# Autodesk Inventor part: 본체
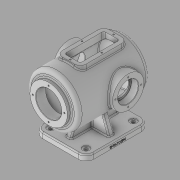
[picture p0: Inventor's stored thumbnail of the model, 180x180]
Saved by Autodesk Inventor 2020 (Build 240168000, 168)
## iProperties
Created: 2021-11
Part Number: 본체
Material: Generic
Document SubType Name: Modeling
Designer: Administrator
Density: 1 g/cm^3
Appearance: Default
Mass: 1311.12 g
Surface Area: 2404.68 cm^2
Volume: 1311.12 cm^3
Author: Administrator
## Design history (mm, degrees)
sketch "스케치1"
  geometry: L1 (-80, -65)-(80, -65); L2 (80, -65)-(80, 65); L3 (80, 65)-(-80, 65); L4 (-80, 65)-(-80, -65); L5 (-80, -65)-(80, 65); L6 (80, -65)-(-80, 65); 1 further point
  constraints: 12 end point, 2 midpoint, 2 parallel, 1 horizontal, 1 perpendicular
  dimensions: "d0" = 160 distance of L2.end L3.end; "d1" = 130 distance of L3.end L1.start
extrude "돌출1" new body sketch "스케치1" distance "d2" = 14; taper "d3" = 0 deg
sketch "스케치2"
  geometry: L1 (100, 179)-(-75.993, 179); L2 (-100, 114)-(110, 114); L3 (100, 179)-(100, 161.5); L4 (100, 161.5)-(110, 161.5); L5 (110, 161.5)-(110, 114); L6 (110, 146.5)-(85, 146.5); L7 (85, 146.5)-(85, 169); L8 (85, 169)-(-71.239, 169); L9 (80, 0)-(80, 14) reference; A1 r 100 centre (0, 114) between (-75.993, 179) and (-75.993, 49); A2 r 90 centre (0, 114) between (-71.239, 169) and (-75.514, 65.035); 2 further points
  constraints: 16 end point, 5 point on circle, 4 perpendicular, 2 centre point, 2 horizontal, 1 concentric, 1 parallel, 1 point on line, 1 vertical, 1 vertical alignment
  dimensions: "d4" = 210 distance of L2.start L2.end; "d5" = 95 diameter of L4 L2; "d6" = 100 radius of A1; "d7" = 114 vertical distance of point (0, 0) L2.end; "d8" = 10 distance of L3.end L4.end; "d9" = 130 diameter of L1 L2; "d10" = 10 radial gap between concentric circles of A1 A2; "d11" = 65 diameter of L6 L2; "d12" = 25 distance of L6.start L6.end; "d13" = 110 diameter of L8 L2; "d125" = 30 horizontal distance of L9.end L2.end
revolve "회전1" stored, may be unused: angle "d14" = 90 deg
sketch "스케치3"
  geometry: L1 (110, 66.5)-(110, 161.5) reference; C1 r 40 at (-17, 114); 2 further points
  constraints: 1 centre point, 1 horizontal alignment, 1 midpoint
  dimensions: "d15" = 80 diameter of C1; "d72" = 127 distance from line of C1.centre L1
extrude "돌출2" join sketch "스케치3" stored distance "d16" = 150; taper "d17" = 0 deg
revolve "회전2" stored, may be unused: angle "d18" = 90 deg
sketch "스케치4"
  geometry: C1 r 40 at (0, 0) reference; 2 further points
  constraints: 1 coincident
hole "구멍1" sketch "스케치4" at (0, 0) diameter "d19" = 42; stored, may be unused: countersink angle "d23" = 90 deg, drill point angle "d25" = 0 deg; dims "d20" = 6, "d21" = 52, "d22" = 18, "d24" = 17
sketch "스케치5"
  geometry: L1 (-7, 7)-(7, 7); L2 (7, 7)-(7, -7); L3 (7, -7)-(-7, -7); L4 (-7, -7)-(-7, 7); L5 (-7, 7)-(7, -7); L6 (7, 7)-(-7, -7); 1 further point
  constraints: 12 end point, 2 midpoint, 2 parallel, 1 horizontal, 1 perpendicular
  dimensions: "d26" = 14 distance of L1.end L2.end; "d27" = 14 distance of L1.start L1.end
extrude "돌출3" join sketch "스케치5" stored distance "d28" = 150; taper "d29" = 0 deg
sketch "스케치6"
  geometry: L1 (-80, 14)-(80, 14) reference; L2 (60, 14)-(49.398, 43.127); L3 (-60, 14)-(-49.812, 41.991); L4 (0, 0)-(0, 31.369)
  constraints: 6 end point, 2 point on line, 1 vertical, 1 other
  dimensions: "d31" = 120 distance of L3.start L2.start; "d32" = 110 deg angle of L1 L2
feature "리브1" dims "d33" = 1, "d34" = 14, "d35" = 0, "d36" = 0, "d37" = 1, "d38" = 1
feature "리브2" dims "d39" = 1, "d40" = 14, "d41" = 0, "d42" = 0, "d43" = 1, "d44" = 1
sketch "스케치7"
  geometry: L1 (-65, 14)-(65, 14) reference; L2 (50, 14)-(37.827, 47.444); L3 (-50, 14)-(-36.039, 52.359); L4 (0, 0)-(0, 44.819)
  constraints: 6 end point, 2 point on line, 1 vertical, 1 other
  dimensions: "d45" = 100 distance of L3.start L2.start; "d46" = 110 deg angle of L1 L2
feature "리브3" dims "d47" = 1, "d48" = 14, "d49" = 0, "d50" = 0, "d51" = 1, "d52" = 1
feature "리브4" dims "d53" = 1, "d54" = 14, "d55" = 0, "d56" = 0, "d57" = 1, "d58" = 1
node "작업 평면1"
sketch "스케치8"
  geometry: L1 (-60, -30)-(60, -30); L2 (60, -30)-(60, 30); L3 (60, 30)-(-60, 30); L4 (-60, 30)-(-60, -30); L5 (-60, -30)-(60, 30); L6 (60, -30)-(-60, 30); L7 (-100, 65)-(-100, -65) reference; L8 (-110, 47.5)-(-110, -47.5) reference; 3 further points
  constraints: 12 end point, 3 midpoint, 2 parallel, 1 coincident, 1 horizontal, 1 perpendicular
  dimensions: "d60" = 120 distance of L2.end L3.end; "d61" = 60 distance of L3.end L1.start; "d103" = 50 distance from line of L8 L3.end
extrude "돌출4" join sketch "스케치8" stored distance "d63" = 150; taper "d64" = 0 deg
sketch "스케치9"
  geometry: L1 (60, 30)-(-60, 30) reference; L2 (-60, 30)-(-60, -30) reference; L3 (-60, -30)-(60, -30) reference; L4 (60, -30)-(60, 30) reference; L5 (-50, 20)-(50, 20); L6 (50, 20)-(50, -20); L7 (50, -20)-(-50, -20); L8 (-50, -20)-(-50, 20)
  constraints: 8 end point, 3 other
  dimensions: "d66" = 10 distance between parallel lines of L1 L5
extrude "돌출5" cut sketch "스케치9" stored distance "d67" = 150; taper "d68" = 0 deg
sketch "스케치10"
  geometry: L1 (60, 30)-(-60, 30) reference; L2 (57, 75)-(-23, 75) reference; L3 (0, 0)-(29.886, 0); 6 further points
  constraints: 2 end point, 2 horizontal alignment, 2 midpoint, 1 horizontal, 1 symmetric about line, 1 vertical alignment
  dimensions: "d69" = 50 distance of point (0, -25) point (0, 25); "d70" = 55 horizontal distance of point (0, 25) point (55, 0); "d71" = 55 horizontal distance of point (-55, 0) point (0, 25); "d73" = 17 horizontal distance of point (17, 75) point (0, 25)
sketch "스케치11" dims "d74" = 80
  geometry: L1 (0, 0)-(40, 0); C1 r 47.5 at (0, 0) reference; 2 further points
  constraints: 2 coincident, 2 end point, 1 horizontal, 1 horizontal alignment, 2 other
hole "구멍2" sketch "스케치11" at (40, 0) diameter "d75" = 3.45873; stored, may be unused: countersink angle "d79" = 90 deg, drill point angle "d81" = 118 deg; dims "d76" = 9, "d77" = 52, "d78" = 18, "d80" = 11
sketch "스케치12"
  geometry: L1 (0, 14)-(160, 14) reference; L2 (0, 0)-(0, 14) reference; L3 (59.261, 8.002)-(100.739, 8.002); L4 (100.739, 8.002)-(100.739, 1.998); L5 (100.739, 1.998)-(59.261, 1.998); L6 (59.261, 1.998)-(59.261, 8.002); L7 (59.261, 8.002)-(100.739, 1.998); L8 (0, 0)-(160, 0) reference; 3 further points
  constraints: 2 end point, 2 midpoint, 1 vertical alignment, 2 other
  dimensions: "d85" = 5 distance of point (80, 0) point (80, 5)
feature "엠보싱1" sketch "스케치12" dims "d13" = 110, "d86" = 0.5, "d87" = 0
fillet "모깎기1" dims "d88" = 10
fillet "모깎기2" dims "d89" = 3
fillet "모깎기3" dims "d90" = 3
fillet "모깎기4" dims "d91" = 20
sketch "스케치13"
  geometry: L1 (-80, 45)-(-80, -45) reference; L2 (60, 65)-(-60, 65) reference; L3 (80, -45)-(80, 45) reference; L4 (-60, -65)-(60, -65) reference; A1 r 20 centre (-60, -45) between (-80, -45) and (-60, -65) reference; A2 r 20 centre (-60, 45) between (-60, 65) and (-80, 45) reference; A3 r 20 centre (60, 45) between (80, 45) and (60, 65) reference; A4 r 20 centre (60, -45) between (60, -65) and (80, -45) reference; 5 further points
  constraints: 4 coincident
hole "구멍3" sketch "스케치13" at (-60, 45), (-60, -45), (60, -45), (60, 45) diameter "d92" = 9; stored, may be unused: countersink angle "d96" = 90 deg, drill point angle "d98" = 0 deg; dims "d93" = 9, "d94" = 18, "d95" = 2, "d97" = 11
fillet "모깎기5" dims "d99" = 0.3
chamfer "모따기1" distance "d100" = 1; stored, may be unused: second distance "d101" = 2, angle "d102" = 45 deg
hole "구멍4" sketch "스케치10" diameter "d104" = 3.45873; stored, may be unused: countersink angle "d108" = 90 deg, drill point angle "d110" = 118 deg; dims "d105" = 9, "d106" = 18, "d107" = 2, "d109" = 11
fillet "모깎기6" dims "d111" = 15, "d113" = 5
fillet "모깎기7" dims "d112" = 3
sketch "스케치14" dims "d114" = 65
  geometry: L1 (0, 0)-(0, 32.5); C1 r 40 at (0, 0) reference; 2 further points
  constraints: 2 coincident, 2 end point, 1 vertical, 1 vertical alignment, 2 other
hole "구멍5" sketch "스케치14" at (0, 32.5) diameter "d115" = 3.45873; stored, may be unused: countersink angle "d119" = 90 deg, drill point angle "d121" = 118 deg; dims "d116" = 11, "d117" = 4, "d118" = 2, "d120" = 13
node "솔리드1"
mirror "미러1"
pattern_circular "원형 패턴1" dims angle "d83" = 360 deg
pattern_circular "원형 패턴2" dims angle "d123" = 360 deg
mirror "미러2"
node "투영된 루프1"
node "투영된 루프2"
feature "A9D066F2-1C7D-4E18-AEED-F7BC21143FA4" dims "d92" = 9, "d93" = 9, "d94" = 18, "d95" = 2, "d96" = 90 deg, "d97" = 11, "d98" = 0
other parameters: "d59" = 184
